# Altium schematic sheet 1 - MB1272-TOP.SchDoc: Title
size A3; CompanyName: Octavo Systems; Address3: Austin, TX; Address4: USA; DocumentNumber: DK2 RefDes; Revision: C-01; SheetNumber: 1; SheetTotal: 14
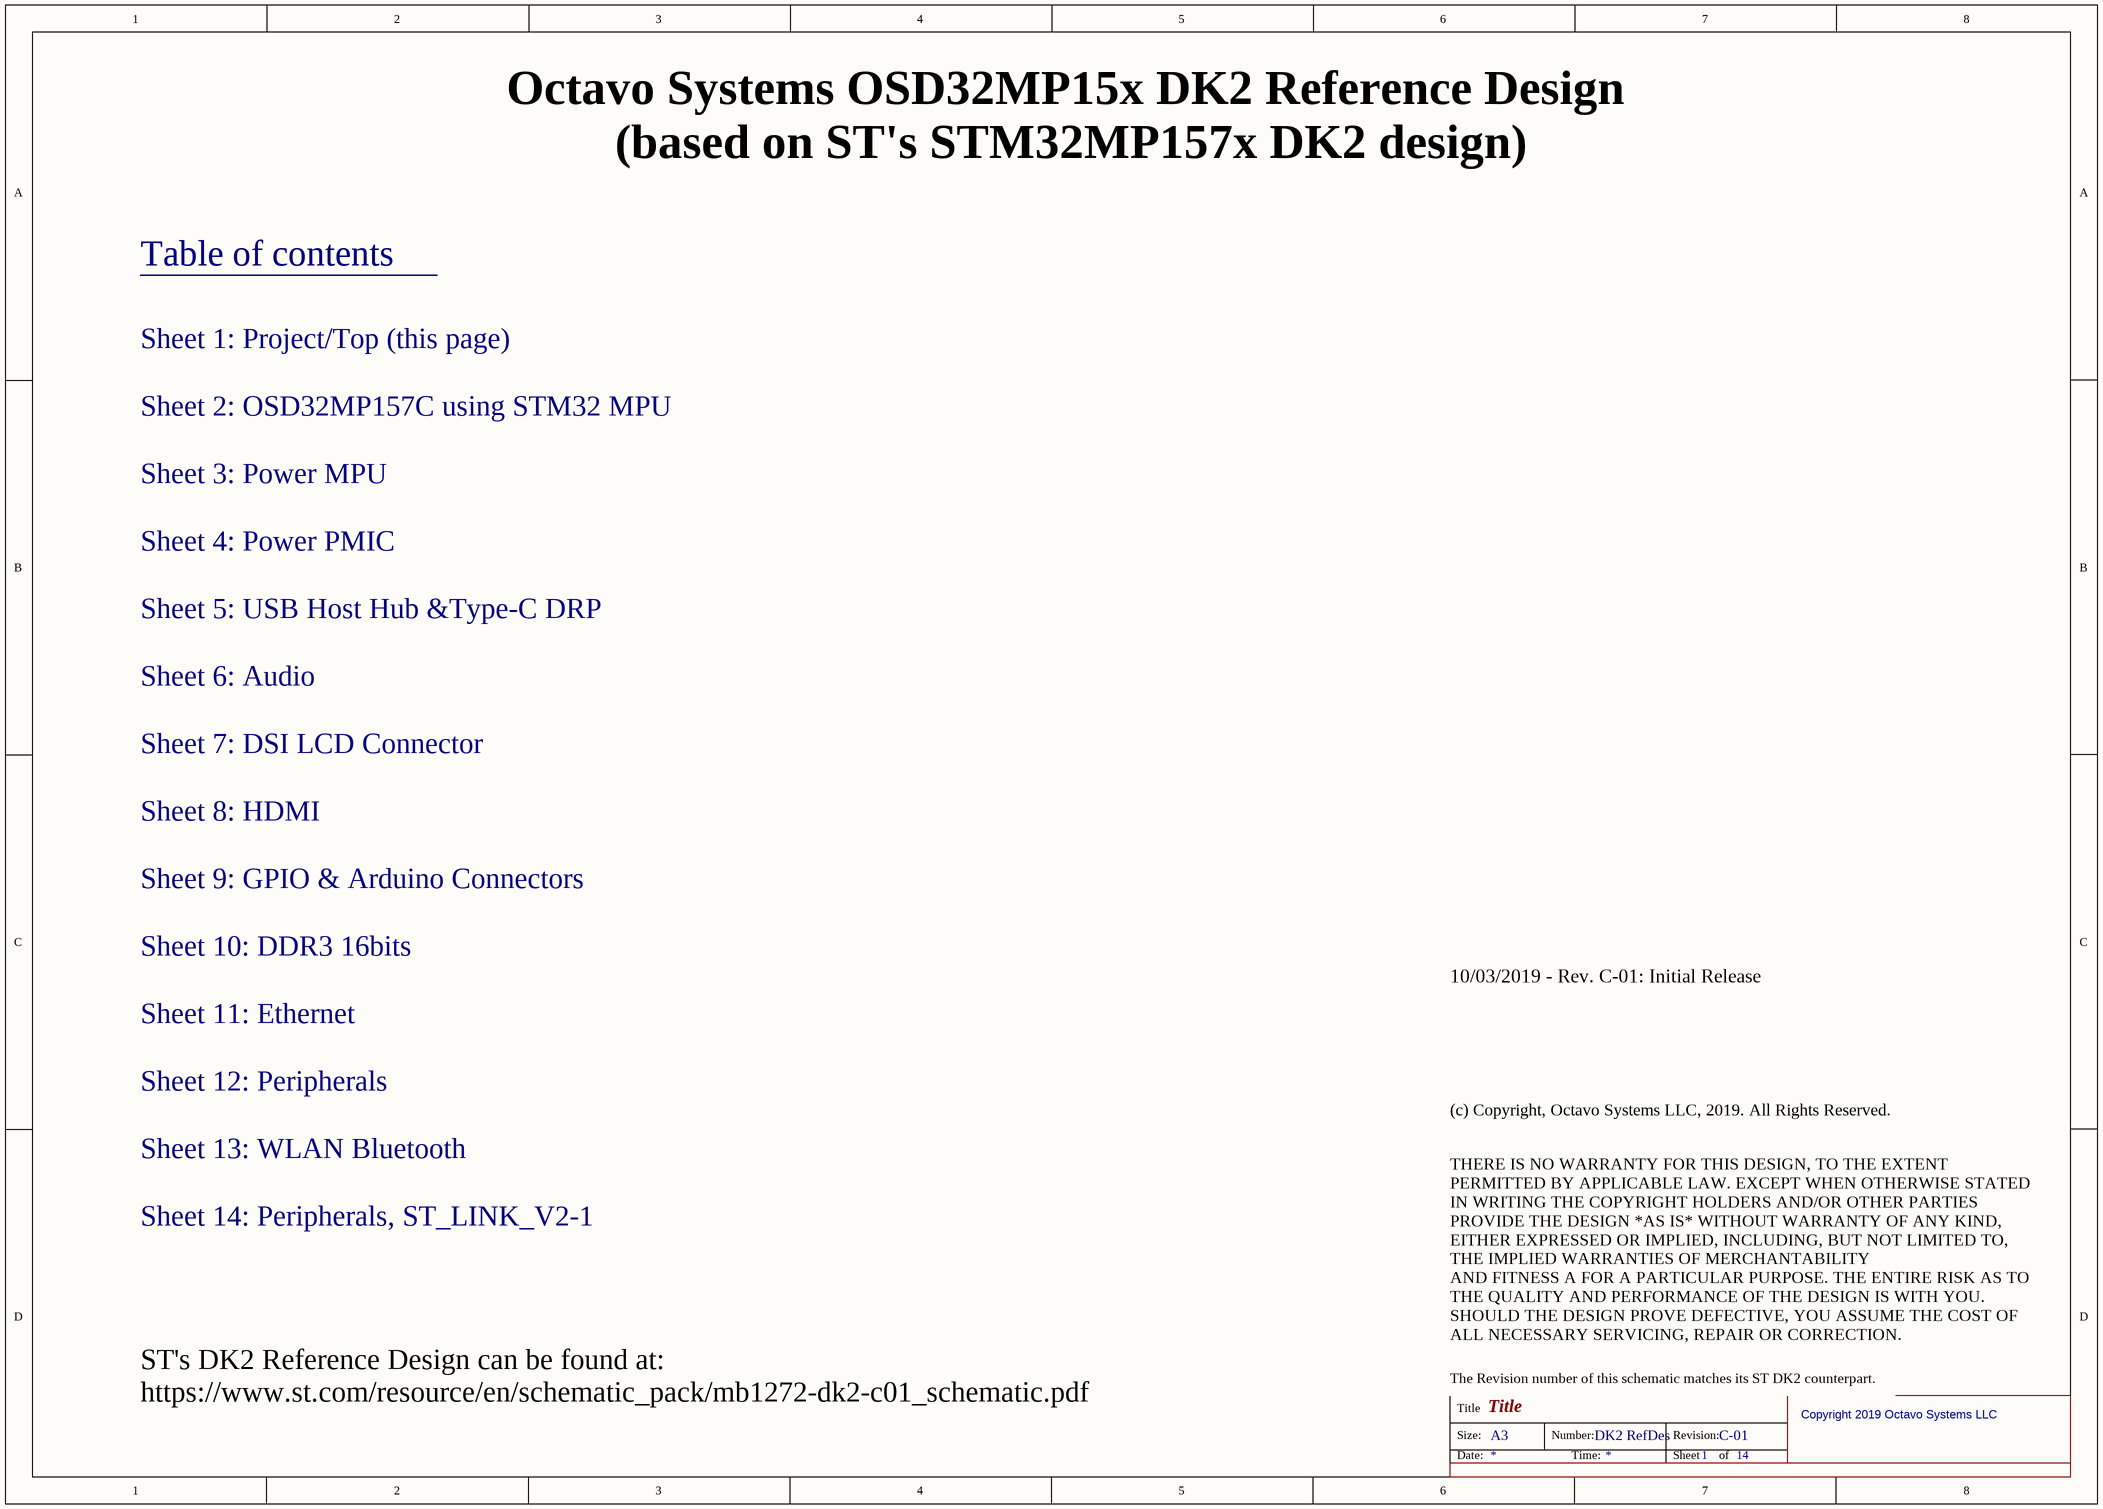
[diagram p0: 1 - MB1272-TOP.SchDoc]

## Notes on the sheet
- Octavo Systems OSD32MP15x DK2 Reference Design
  (based on ST's STM32MP157x DK2 design)
- Table of contents
- Sheet 1: Project/Top (this page)
- Sheet 2: OSD32MP157C using STM32 MPU
- Sheet 3: Power MPU
- Sheet 4: Power PMIC
- Sheet 5: USB Host Hub &Type-C DRP
- Sheet 6: Audio
- Sheet 7: DSI LCD Connector
- Sheet 8: HDMI
- Sheet 9: GPIO & Arduino Connectors
- Sheet 10: DDR3 16bits
- Sheet 11: Ethernet
- Sheet 12: Peripherals
- (c) Copyright, Octavo Systems LLC, 2019. All Rights Reserved.
- 10/03/2019 - Rev. C-01: Initial Release
- Sheet 13: WLAN Bluetooth
- Sheet 14: Peripherals, ST_LINK_V2-1
- THERE IS NO WARRANTY FOR THIS DESIGN, TO THE EXTENT PERMITTED BY APPLICABLE LAW. EXCEPT WHEN OTHERWISE STATED IN WRITING THE COPYRIGHT HOLDERS AND/OR OTHER PARTIES PROVIDE THE DESIGN *AS IS* WITHOUT WARRANTY OF ANY KIND, EITHER EXPRESSED OR IMPLIED, INCLUDING, BUT NOT LIMITED TO, THE IMPLIED WARRANTIES OF MERCHANTABILITY
  AND FITNESS A FOR A PARTICULAR PURPOSE. THE ENTIRE RISK AS TO THE QUALITY AND PERFORMANCE OF THE DESIGN IS WITH YOU. SHOULD THE DESIGN PROVE DEFECTIVE, YOU ASSUME THE COST OF ALL NECESSARY SERVICING, REPAIR OR CORRECTION.
- The Revision number of this schematic matches its ST DK2 counterpart.
- ST's DK2 Reference Design can be found at: https://www.st.com/resource/en/schematic_pack/mb1272-dk2-c01_schematic.pdf
- Copyright 2019 Octavo Systems LLC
